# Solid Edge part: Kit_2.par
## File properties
Author: bmolnar
Last saved by: ahadarics
Revision: 76
Sűrűség: 0,000 kg/m^3
Pontosság: 0,990
Username: bmolnar
Dokumentum tartalom típus: 0
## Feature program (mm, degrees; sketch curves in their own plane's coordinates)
base feature "unnamed BaseFeature 1"
thread "unnamed Thread 1"
sketch for "unnamed Hole 1" plane through (-36, -36, 14) normal (0, 0, 1) x-axis (0, 1, 0)
  hole centre (0, 0) bore radius 4.188
hole "unnamed Hole 1" through
sketch for "unnamed Hole 2" plane through (-36, -36, 14) normal (0, 0, 1) x-axis (0, 1, 0)
  hole centre (72, 0) bore radius 4.188
hole "unnamed Hole 2" through
sketch for "unnamed Hole 3" plane through (-36, -36, 14) normal (0, 0, 1) x-axis (0, 1, 0)
  hole centre (72, -72) bore radius 4.188
hole "unnamed Hole 3" through
sketch for "unnamed Hole 4" plane through (-36, -36, 14) normal (0, 0, 1) x-axis (0, 1, 0)
  hole centre (0, -72) bore radius 4.188
hole "unnamed Hole 4" through
pattern "unnamed Pattern 1" of "unnamed Hole 1", "unnamed Hole 2", "unnamed Hole 3", "unnamed Hole 4"
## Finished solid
Body 1: solid body, 294 faces, 719 edges, 443 vertices.
  Faces by surface: plane 138, cylinder 72, swept 60, cone 15, torus 8, spline 1
  Edges by curve: line 421, circle 137, spline 120, ellipse 32, curve on surface 8, intersection 1
Bounding box of the edges (mm; curved faces can reach further): 95.500 x 95.500 x 15.000, from (-47.75, -47.75, 2) to (47.75, 47.75, 17).
Cylindrical faces by radius (mm): R0.2 x48, R0.2017 x2, R0.2018 x2, R2.5 x1, R4.188 x4, R4.283 x1, R4.9 x4, R5.15 x4, R6 x1, R6.75 x4, R21.1047 x1
Conical faces (half-angle, radius in mm at the cone's reference point): 0.5 deg R10 x4, 0.5 deg R13.5 x2, 45 deg R4.185 x4, 45 deg R4.985 x4, 45 deg R6.25 x1
Toroidal faces (ring radius, tube radius in mm): R4.7 r0.2 x8
Planar faces by outward normal: +x 14, +y 13, +z 18, -x 17, -y 14, -z 1, oblique 61
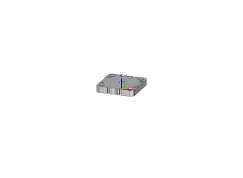
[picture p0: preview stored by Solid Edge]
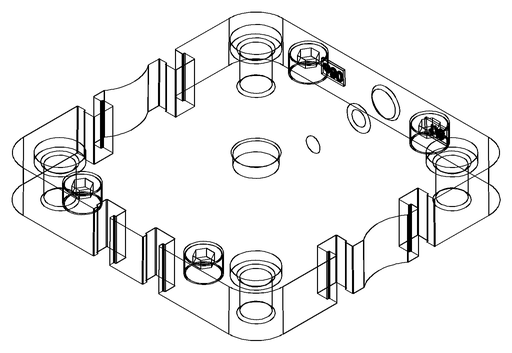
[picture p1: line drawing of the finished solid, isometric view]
